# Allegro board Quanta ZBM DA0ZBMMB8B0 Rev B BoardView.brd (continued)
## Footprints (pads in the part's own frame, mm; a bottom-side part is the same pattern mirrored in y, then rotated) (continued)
BGA153-HYNIX-H26M62002JPR-0_5S
  round 0.254 smd: A1(-3.25,-3.25) A2(-3.25,-2.75) A3(-3.25,-2.25) A4(-3.25,-1.75) A5(-3.25,-1.25) A6(-3.25,-0.75) A7(-3.25,-0.25) A8(-3.25,0.25) A9(-3.25,0.75) A10(-3.25,1.25) A11(-3.25,1.75) A12(-3.25,2.25) A13(-3.25,2.75) A14(-3.25,3.25) B1(-2.75,-3.25) B2(-2.75,-2.75) B3(-2.75,-2.25) B4(-2.75,-1.75) B5(-2.75,-1.25) B6(-2.75,-0.75) B7(-2.75,-0.25) B8(-2.75,0.25) B9(-2.75,0.75) B10(-2.75,1.25) B11(-2.75,1.75) B12(-2.75,2.25) B13(-2.75,2.75) B14(-2.75,3.25) C1(-2.25,-3.25) C2(-2.25,-2.75) C3(-2.25,-2.25) C4(-2.25,-1.75) C5(-2.25,-1.25) C6(-2.25,-0.75) C7(-2.25,-0.25) C8(-2.25,0.25) C9(-2.25,0.75) C10(-2.25,1.25) C11(-2.25,1.75) C12(-2.25,2.25) C13(-2.25,2.75) C14(-2.25,3.25) D1(-1.75,-3.25) D2(-1.75,-2.75) D3(-1.75,-2.25) D4(-1.75,-1.75) D12(-1.75,2.25) D13(-1.75,2.75) D14(-1.75,3.25) E1(-1.25,-3.25) E2(-1.25,-2.75) E3(-1.25,-2.25) E5(-1.25,-1.25) E6(-1.25,-0.75) E7(-1.25,-0.25) E8(-1.25,0.25) E9(-1.25,0.75) E10(-1.25,1.25) E12(-1.25,2.25) E13(-1.25,2.75) E14(-1.25,3.25) F1(-0.75,-3.25) F2(-0.75,-2.75) F3(-0.75,-2.25) F5(-0.75,-1.25) F10(-0.75,1.25) F12(-0.75,2.25) F13(-0.75,2.75) F14(-0.75,3.25) G1(-0.25,-3.25) G2(-0.25,-2.75) G3(-0.25,-2.25) G5(-0.25,-1.25) G10(-0.25,1.25) G12(-0.25,2.25) G13(-0.25,2.75) G14(-0.25,3.25) H1(0.25,-3.25) H2(0.25,-2.75) H3(0.25,-2.25) H5(0.25,-1.25) H10(0.25,1.25) H12(0.25,2.25) H13(0.25,2.75) H14(0.25,3.25) J1(0.75,-3.25) J2(0.75,-2.75) J3(0.75,-2.25) J5(0.75,-1.25) J10(0.75,1.25) J12(0.75,2.25) J13(0.75,2.75) J14(0.75,3.25) K1(1.25,-3.25) K2(1.25,-2.75) K3(1.25,-2.25) K5(1.25,-1.25) K6(1.25,-0.75) K7(1.25,-0.25) K8(1.25,0.25) K9(1.25,0.75) K10(1.25,1.25) K12(1.25,2.25) K13(1.25,2.75) K14(1.25,3.25) L1(1.75,-3.25) L2(1.75,-2.75) L3(1.75,-2.25) L12(1.75,2.25) L13(1.75,2.75) L14(1.75,3.25) M1(2.25,-3.25) M2(2.25,-2.75) M3(2.25,-2.25) M4(2.25,-1.75) M5(2.25,-1.25) M6(2.25,-0.75) M7(2.25,-0.25) M8(2.25,0.25) M9(2.25,0.75) M10(2.25,1.25) M11(2.25,1.75) M12(2.25,2.25) M13(2.25,2.75) M14(2.25,3.25) N1(2.75,-3.25) N2(2.75,-2.75) N3(2.75,-2.25) N4(2.75,-1.75) N5(2.75,-1.25) N6(2.75,-0.75) N7(2.75,-0.25) N8(2.75,0.25) N9(2.75,0.75) N10(2.75,1.25) N11(2.75,1.75) N12(2.75,2.25) N13(2.75,2.75) N14(2.75,3.25) P1(3.25,-3.25) P2(3.25,-2.75) P3(3.25,-2.25) P4(3.25,-1.75) P5(3.25,-1.25) P6(3.25,-0.75) P7(3.25,-0.25) P8(3.25,0.25) P9(3.25,0.75) P10(3.25,1.25) P11(3.25,1.75) P12(3.25,2.25) P13(3.25,2.75) P14(3.25,3.25)
BGA200-HYNIX-H9HCNNNCPMMLXR-0_5S
  round 0.254 smd: A1(-6.825,-4.4) A2(-6.825,-3.6) A3(-6.825,-2.8) A4(-6.825,-2) A5(-6.825,-1.2) A8(-6.825,1.2) A9(-6.825,2) A10(-6.825,2.8) A11(-6.825,3.6) A12(-6.825,4.4) AA1(6.175,-4.4) AA2(6.175,-3.6) AA3(6.175,-2.8) AA4(6.175,-2) AA5(6.175,-1.2) AA8(6.175,1.2) AA9(6.175,2) AA10(6.175,2.8) AA11(6.175,3.6) AA12(6.175,4.4) AB1(6.825,-4.4) AB2(6.825,-3.6) AB3(6.825,-2.8) AB4(6.825,-2) AB5(6.825,-1.2) AB8(6.825,1.2) AB9(6.825,2) AB10(6.825,2.8) AB11(6.825,3.6) AB12(6.825,4.4) B1(-6.175,-4.4) B2(-6.175,-3.6) B3(-6.175,-2.8) B4(-6.175,-2) B5(-6.175,-1.2) B8(-6.175,1.2) B9(-6.175,2) B10(-6.175,2.8) B11(-6.175,3.6) B12(-6.175,4.4) C1(-5.525,-4.4) C2(-5.525,-3.6) C3(-5.525,-2.8) C4(-5.525,-2) C5(-5.525,-1.2) C8(-5.525,1.2) C9(-5.525,2) C10(-5.525,2.8) C11(-5.525,3.6) C12(-5.525,4.4) D1(-4.875,-4.4) D2(-4.875,-3.6) D3(-4.875,-2.8) D4(-4.875,-2) D5(-4.875,-1.2) D8(-4.875,1.2) D9(-4.875,2) D10(-4.875,2.8) D11(-4.875,3.6) D12(-4.875,4.4) E1(-4.225,-4.4) E2(-4.225,-3.6) E3(-4.225,-2.8) E4(-4.225,-2) E5(-4.225,-1.2) E8(-4.225,1.2) E9(-4.225,2) E10(-4.225,2.8) E11(-4.225,3.6) E12(-4.225,4.4) F1(-3.575,-4.4) F2(-3.575,-3.6) F3(-3.575,-2.8) F4(-3.575,-2) F5(-3.575,-1.2) F8(-3.575,1.2) F9(-3.575,2) F10(-3.575,2.8) F11(-3.575,3.6) F12(-3.575,4.4) G1(-2.925,-4.4) G2(-2.925,-3.6) G3(-2.925,-2.8) G4(-2.925,-2) G5(-2.925,-1.2) G8(-2.925,1.2) G9(-2.925,2) G10(-2.925,2.8) G11(-2.925,3.6) G12(-2.925,4.4) H1(-2.275,-4.4) H2(-2.275,-3.6) H3(-2.275,-2.8) H4(-2.275,-2) H5(-2.275,-1.2) H8(-2.275,1.2) H9(-2.275,2) H10(-2.275,2.8) H11(-2.275,3.6) H12(-2.275,4.4) J1(-1.625,-4.4) J2(-1.625,-3.6) J3(-1.625,-2.8) J4(-1.625,-2) J5(-1.625,-1.2) J8(-1.625,1.2) J9(-1.625,2) J10(-1.625,2.8) J11(-1.625,3.6) J12(-1.625,4.4) K1(-0.975,-4.4) K2(-0.975,-3.6) K3(-0.975,-2.8) K4(-0.975,-2) K5(-0.975,-1.2) K8(-0.975,1.2) K9(-0.975,2) K10(-0.975,2.8) K11(-0.975,3.6) K12(-0.975,4.4) N1(0.975,-4.4) N2(0.975,-3.6) N3(0.975,-2.8) N4(0.975,-2) N5(0.975,-1.2) N8(0.975,1.2) N9(0.975,2) N10(0.975,2.8) N11(0.975,3.6) N12(0.975,4.4) P1(1.625,-4.4) P2(1.625,-3.6) P3(1.625,-2.8) P4(1.625,-2) P5(1.625,-1.2) P8(1.625,1.2) P9(1.625,2) P10(1.625,2.8) P11(1.625,3.6) P12(1.625,4.4) R1(2.275,-4.4) R2(2.275,-3.6) R3(2.275,-2.8) R4(2.275,-2) R5(2.275,-1.2) R8(2.275,1.2) R9(2.275,2) R10(2.275,2.8) R11(2.275,3.6) R12(2.275,4.4) T1(2.925,-4.4) T2(2.925,-3.6) T3(2.925,-2.8) T4(2.925,-2) T5(2.925,-1.2) T8(2.925,1.2) T9(2.925,2) T10(2.925,2.8) T11(2.925,3.6) T12(2.925,4.4) U1(3.575,-4.4) U2(3.575,-3.6) U3(3.575,-2.8) U4(3.575,-2) U5(3.575,-1.2) U8(3.575,1.2) U9(3.575,2) U10(3.575,2.8) U11(3.575,3.6) U12(3.575,4.4) V1(4.225,-4.4) V2(4.225,-3.6) V3(4.225,-2.8) V4(4.225,-2) V5(4.225,-1.2) V8(4.225,1.2) V9(4.225,2) V10(4.225,2.8) V11(4.225,3.6) V12(4.225,4.4) W1(4.875,-4.4) W2(4.875,-3.6) W3(4.875,-2.8) W4(4.875,-2) W5(4.875,-1.2) W8(4.875,1.2) W9(4.875,2) W10(4.875,2.8) W11(4.875,3.6) W12(4.875,4.4) Y1(5.525,-4.4) Y2(5.525,-3.6) Y3(5.525,-2.8) Y4(5.525,-2) Y5(5.525,-1.2) Y8(5.525,1.2) Y9(5.525,2) Y10(5.525,2.8) Y11(5.525,3.6) Y12(5.525,4.4)
BGA1338-INTEL-JSL
  round 0.356 smd: A4(-16.815,-10.196) A49(-16.815,10.306) A51(-16.815,10.953) B3(-16.255,-10.755) B52(-16.344,11.315) C50(-16.186,10.743) CN1(15.696,-11.315) CN52(15.689,11.315) CP3(16.181,-10.681) CR1(16.352,-11.314) CR50(16.27,10.719) CR52(16.337,11.315) CT2(16.815,-10.843) CT4(16.815,-10.195) CT49(16.815,10.306) CT51(16.815,10.953) D1(-15.696,-11.315) D52(-15.696,11.315)
  round 0.33 smd: A5(-16.815,-9.561) A48(-16.815,9.663) AB17(-7.567,-4.436) AB18(-7.567,-3.712) AB20(-7.567,-2.988) AB21(-7.567,-2.264) AB23(-7.567,-1.541) AB25(-7.567,-0.817) AB33(-7.567,2.803) AB34(-7.567,3.527) AB36(-7.567,4.251) AC17(-6.805,-4.436) AC18(-6.805,-3.712) AC20(-6.805,-2.988) AC21(-6.805,-2.264) AC23(-6.805,-1.541) AC25(-6.805,-0.817) AC33(-6.805,2.803) AC34(-6.805,3.527) AC36(-6.805,4.251) AE17(-6.043,-4.436) AE18(-6.043,-3.712) AE33(-6.043,2.803) AE34(-6.043,3.527) AE36(-6.043,4.251) AG17(-5.281,-4.436) AG18(-5.281,-3.712) AG33(-5.281,2.803) AG34(-5.281,3.527) AG36(-5.281,4.251) AH17(-4.519,-4.436) AH18(-4.519,-3.712) AH33(-4.519,2.803) AH34(-4.519,3.527) AH36(-4.519,4.251) AK17(-3.757,-4.436) AK18(-3.757,-3.712) AK33(-3.757,2.803) AK34(-3.757,3.527) AK36(-3.757,4.251) AM17(-2.995,-4.436) AM18(-2.995,-3.712) AM33(-2.995,2.803) AM34(-2.995,3.527) AM36(-2.995,4.251) AP17(-2.233,-4.436) AP18(-2.233,-3.712) AP33(-2.233,2.803) AP34(-2.233,3.527) AP36(-2.233,4.251) AR17(-1.471,-4.436) AR18(-1.471,-3.712) AR33(-1.471,2.803) AR34(-1.471,3.527) AR36(-1.471,4.251) AU17(-0.709,-4.436) AU18(-0.709,-3.712) AU33(-0.709,2.803) AU34(-0.709,3.527) AU36(-0.709,4.251) AW17(0.053,-4.436) AW18(0.053,-3.712) AW33(0.053,2.803) AW34(0.053,3.527) AW36(0.053,4.251) AY17(0.815,-4.436) AY18(0.815,-3.712) AY20(0.815,-2.988) AY21(0.815,-2.264) AY23(0.815,-1.541) AY33(0.815,2.803) AY34(0.815,3.527) AY36(0.815,4.251) B4(-16.222,-10.162) B5(-16.221,-9.567) BB17(1.577,-4.436) BB18(1.577,-3.712) BB20(1.577,-2.988) BB21(1.577,-2.264) BB23(1.577,-1.541) BB33(1.577,2.803) BB34(1.577,3.527) BB36(1.577,4.251) BD17(2.339,-4.436) BD18(2.339,-3.712) BD20(2.339,-2.988) BD21(2.339,-2.264) BD23(2.339,-1.541) BD33(2.339,2.803) BD34(2.339,3.527) BD36(2.339,4.251) BE17(3.101,-4.436) BE18(3.101,-3.712) BE20(3.101,-2.988) BE21(3.101,-2.264) BE23(3.101,-1.541) BE33(3.101,2.803) BE34(3.101,3.527) BE36(3.101,4.251) BG17(3.863,-4.436) BG18(3.863,-3.712) BG20(3.863,-2.988) BG21(3.863,-2.264) BG23(3.863,-1.541) BG33(3.863,2.803) BG34(3.863,3.527) BG36(3.863,4.251) BJ17(4.625,-4.436) BJ18(4.625,-3.712) BJ20(4.625,-2.988) BJ21(4.625,-2.264) BJ23(4.625,-1.541) BJ33(4.625,2.803) BJ34(4.625,3.527) BJ36(4.625,4.251) BK17(5.387,-4.436) BK18(5.387,-3.712) BK20(5.387,-2.988) BK21(5.387,-2.264) BK23(5.387,-1.541) BK33(5.387,2.803) BK34(5.387,3.527) BK36(5.387,4.251) BM17(6.149,-4.436) BM18(6.149,-3.712) BM20(6.149,-2.988) BM21(6.149,-2.264) BM23(6.149,-1.541) BM33(6.149,2.803) BM34(6.149,3.527) BM36(6.149,4.251) BP17(6.911,-4.436) BP18(6.911,-3.712) BP20(6.911,-2.988) BP21(6.911,-2.264) BP23(6.911,-1.541) BP33(6.911,2.803) BP34(6.911,3.527) BP36(6.911,4.251) BT17(7.673,-4.436) BT18(7.673,-3.712) BT20(7.673,-2.988) BT21(7.673,-2.264) BT23(7.673,-1.541) BT25(7.673,-0.817) BT26(7.673,-0.093) BT28(7.673,0.631) BT30(7.673,1.355) BT31(7.673,2.079) BT33(7.673,2.803) BT34(7.673,3.527) BT36(7.673,4.251) BU17(8.435,-4.436) BU18(8.435,-3.712) BU20(8.435,-2.988) BU21(8.435,-2.264) BU23(8.435,-1.541) BU25(8.435,-0.817) BU26(8.435,-0.093) BU28(8.435,0.631) BU30(8.435,1.355) BU31(8.435,2.079) BU33(8.435,2.803) BU34(8.435,3.527) BU36(8.435,4.251) BW17(9.197,-4.436) BW18(9.197,-3.712) BW20(9.197,-2.988) BW21(9.197,-2.264) BW23(9.197,-1.541) BW25(9.197,-0.817) BW26(9.197,-0.093) BW28(9.197,0.631) BW30(9.197,1.355) BW31(9.197,2.079) BW33(9.197,2.803) BW34(9.197,3.527) BW36(9.197,4.251) C48(-16.181,9.552) C49(-16.186,10.146) CA17(9.959,-4.436) CA18(9.959,-3.712) CA20(9.959,-2.988) CA21(9.959,-2.264) CA23(9.959,-1.541) CA25(9.959,-0.817) CA26(9.959,-0.093) CA28(9.959,0.631) CA30(9.959,1.355) CA31(9.959,2.079) CA33(9.959,2.803) CA34(9.959,3.527) CA36(9.959,4.251) CM1(15.048,-11.315) CM3(14.886,-10.681) CM50(14.975,10.719) CM52(15.053,11.315) CN3(15.533,-10.681) CN50(15.622,10.719) CP4(16.181,-10.043) CP6(16.181,-9.406) CP48(16.181,9.516) CR49(16.243,10.122) CT5(16.815,-9.55) CT48(16.815,9.658) D3(-15.66,-10.72) D50(-15.585,10.722) E1(-15.048,-11.315) E3(-15.066,-10.72) E50(-14.975,10.722) E52(-15.048,11.315) U17(-9.853,-4.436) U18(-9.853,-3.712) U20(-9.853,-2.988) U21(-9.853,-2.264) U23(-9.853,-1.541) U25(-9.853,-0.817) U26(-9.853,-0.093) U28(-9.853,0.631) U30(-9.853,1.355) U31(-9.853,2.079) U33(-9.853,2.803) U34(-9.853,3.527) U36(-9.853,4.251) V17(-9.091,-4.436) V18(-9.091,-3.712) V20(-9.091,-2.988) V21(-9.091,-2.264) V23(-9.091,-1.541) V25(-9.091,-0.817) V26(-9.091,-0.093) V28(-9.091,0.631) V30(-9.091,1.355) V31(-9.091,2.079) V33(-9.091,2.803) V34(-9.091,3.527) V36(-9.091,4.251) Y17(-8.329,-4.436) Y18(-8.329,-3.712) Y20(-8.329,-2.988) Y21(-8.329,-2.264) Y23(-8.329,-1.541) Y25(-8.329,-0.817) Y33(-8.329,2.803) Y34(-8.329,3.527) Y36(-8.329,4.251)
  round 0.305 smd: A7(-16.815,-8.951) A47(-16.815,9.015) AB6(-7.552,-9.208) AB8(-7.552,-8.548) AB9(-7.552,-7.888) AB10(-7.552,-7.228) AB12(-7.552,-6.567) AB13(-7.552,-5.907) AB15(-7.552,-5.247) AB38(-7.234,5.016) AB39(-7.234,5.676) AB41(-7.234,6.337) AB42(-7.234,6.997) AB44(-7.234,7.657) AB45(-7.234,8.317) AD6(-6.472,-9.208) AD8(-6.472,-8.548) AD9(-6.472,-7.888) AD10(-6.472,-7.228) AD12(-6.472,-6.567) AD13(-6.472,-5.907) AD15(-6.472,-5.247) AD38(-6.332,5.016) AD39(-6.332,5.676) AD41(-6.332,6.337) AD42(-6.332,6.997) AD44(-6.332,7.657) AD45(-6.332,8.317) AF38(-5.431,5.016) AF39(-5.431,5.676) AF41(-5.431,6.337) AF42(-5.431,6.997) AF44(-5.431,7.657) AF45(-5.431,8.317) AG6(-5.215,-9.208) AG8(-5.215,-8.548) AG9(-5.215,-7.888) AG10(-5.215,-7.228) AG12(-5.215,-6.567) AG13(-5.215,-5.907) AG15(-5.215,-5.247) AH38(-4.529,5.016) AH39(-4.529,5.676) AH41(-4.529,6.337) AH42(-4.529,6.997) AH44(-4.529,7.657) AH45(-4.529,8.317) AJ6(-4.136,-9.208) AJ8(-4.136,-8.548) AJ9(-4.136,-7.888) AJ10(-4.136,-7.228) AJ12(-4.136,-6.567) AJ13(-4.136,-5.907) AJ15(-4.136,-5.247) AK38(-3.627,5.016) AK39(-3.627,5.676) AK41(-3.627,6.337) AK42(-3.627,6.997) AK44(-3.627,7.657) AK45(-3.627,8.317) AM6(-2.879,-9.208) AM8(-2.879,-8.548) AM9(-2.879,-7.888) AM10(-2.879,-7.228) AM12(-2.879,-6.567) AM13(-2.879,-5.907) AM15(-2.879,-5.247) AM38(-2.726,5.016) AM39(-2.726,5.676) AM41(-2.726,6.337) AM42(-2.726,6.997) AM44(-2.726,7.657) AM45(-2.726,8.317) AP38(-1.824,5.016) AP39(-1.824,5.676) AP41(-1.824,6.337) AP42(-1.824,6.997) AP44(-1.824,7.657) AP45(-1.824,8.317) AR6(-1.799,-9.208) AR8(-1.799,-8.548) AR9(-1.799,-7.888) AR10(-1.799,-7.228) AR12(-1.799,-6.567) AR13(-1.799,-5.907) AR15(-1.799,-5.247) AT38(-0.923,5.016) AT39(-0.923,5.676) AT41(-0.923,6.337) AT42(-0.923,6.997) AT44(-0.923,7.657) AT45(-0.923,8.317) AU6(-0.542,-9.208) AU8(-0.542,-8.548) AU9(-0.542,-7.888) AU10(-0.542,-7.228) AU12(-0.542,-6.567) AU13(-0.542,-5.907) AU15(-0.542,-5.247) AV38(-0.021,5.016) AV39(-0.021,5.676) AV41(-0.021,6.337) AV42(-0.021,6.997) AV44(-0.021,7.657) AV45(-0.021,8.317) AW6(0.36,-9.208) AW8(0.36,-8.548) AW9(0.36,-7.888) AW10(0.36,-7.228) AW12(0.36,-6.567) AW13(0.36,-5.907) AW15(0.36,-5.247) AY38(0.881,5.016) AY39(0.881,5.676) AY41(0.881,6.337) AY42(0.881,6.997) AY44(0.881,7.657) AY45(0.881,8.317) B7(-16.221,-8.974) BA6(1.274,-9.208) BA8(1.274,-8.548) BA9(1.274,-7.888) BA10(1.274,-7.228) BA12(1.274,-6.567) BA13(1.274,-5.907) BA15(1.274,-5.247) BB38(1.782,5.016) BB39(1.782,5.676) BB41(1.782,6.337) BB42(1.782,6.997) BB44(1.782,7.657) BB45(1.782,8.317) BC6(2.176,-9.208) BC8(2.176,-8.548) BC9(2.176,-7.888) BC10(2.176,-7.228) BC12(2.176,-6.567) BC13(2.176,-5.907) BC15(2.176,-5.247) BD38(2.684,5.016) BD39(2.684,5.676) BD41(2.684,6.337) BD42(2.684,6.997) BD44(2.684,7.657) BD45(2.684,8.317) BF6(3.433,-9.208) BF8(3.433,-8.548) BF9(3.433,-7.888) BF10(3.433,-7.228) BF12(3.433,-6.567) BF13(3.433,-5.907) BF15(3.433,-5.247) BF38(3.585,5.016) BF39(3.585,5.676) BF41(3.585,6.337) BF42(3.585,6.997) BF44(3.585,7.657) BF45(3.585,8.317) BH38(4.487,5.016) BH39(4.487,5.676) BH41(4.487,6.337) BH42(4.487,6.997) BH44(4.487,7.657) BH45(4.487,8.317) BJ6(4.512,-9.208) BJ8(4.512,-8.548) BJ9(4.512,-7.888) BJ10(4.512,-7.228) BJ12(4.512,-6.567) BJ13(4.512,-5.907) BJ15(4.512,-5.247) BK38(5.389,5.016) BK39(5.389,5.676) BK41(5.389,6.337) BK42(5.389,6.997) BK44(5.389,7.657) BK45(5.389,8.317) BL6(5.769,-9.208) BL8(5.769,-8.548) BL9(5.769,-7.888) BL10(5.769,-7.228) BL12(5.769,-6.567) BL13(5.769,-5.907) BL15(5.769,-5.247) BM38(6.29,5.016) BM39(6.29,5.676) BM41(6.29,6.337) BM42(6.29,6.997) BM44(6.29,7.657) BM45(6.29,8.317) BP6(6.849,-9.208) BP8(6.849,-8.548) BP9(6.849,-7.888) BP10(6.849,-7.228) BP12(6.849,-6.567) BP13(6.849,-5.907) BP15(6.849,-5.247) BP38(7.192,5.016) BP39(7.192,5.676) BP41(7.192,6.337) BP42(7.192,6.997) BP44(7.192,7.657) BP45(7.192,8.317) BT38(8.093,5.016) BT39(8.093,5.676) BT41(8.093,6.337) BT42(8.093,6.997) BT44(8.093,7.657) BT45(8.093,8.317) BU6(8.106,-9.208) BU8(8.106,-8.548) BU9(8.106,-7.888) BU10(8.106,-7.228) BU12(8.106,-6.567) BU13(8.106,-5.907) BU15(8.106,-5.247) BV38(8.995,5.016) BV39(8.995,5.676) BV41(8.995,6.337) BV42(8.995,6.997) BV44(8.995,7.657) BV45(8.995,8.317) BW6(9.008,-9.208) BW8(9.008,-8.548) BW9(9.008,-7.888) BW10(9.008,-7.228) BW12(9.008,-6.567) BW13(9.008,-5.907) BW15(9.008,-5.247) BY38(9.897,5.016) BY39(9.897,5.676) BY41(9.897,6.337) BY42(9.897,6.997) BY44(9.897,7.657) BY45(9.897,8.317) C46(-16.181,8.913) CA6(9.909,-9.208) CA8(9.909,-8.548) CA9(9.909,-7.888) CA10(9.909,-7.228) CA12(9.909,-6.567) CA13(9.909,-5.907) CA15(9.909,-5.247) CB17(10.553,-4.437) CB19(10.553,-3.536) CB21(10.553,-2.634) CB23(10.553,-1.733) CB24(10.553,-1.022) CB26(10.553,-0.12) CB28(10.553,0.782) CB30(10.553,1.683) CB32(10.553,2.585) CB34(10.553,3.486) CB36(10.553,4.388) CC6(10.811,-9.258) CC7(10.811,-8.598) CC9(10.811,-7.938) CC11(11.122,-7.142) CC13(11.122,-6.241) CC15(11.122,-5.339) CC17(11.213,-4.437) CC19(11.213,-3.536) CC21(11.213,-2.634) CC23(11.213,-1.733) CC24(11.213,-1.022) CC26(11.213,-0.12) CC28(11.213,0.782) CC30(11.213,1.683) CC32(11.213,2.585) CC34(11.213,3.486) CC36(11.213,4.388) CC38(10.798,5.016) CC39(10.798,5.676) CC41(10.798,6.337) CC42(10.798,6.997) CC44(10.798,7.657) CC45(10.798,8.317) CD6(11.653,-9.262) CD7(11.673,-8.66) CD38(11.292,5.346) CD41(11.39,6.401) CD42(11.393,6.996) CE9(11.782,-8.044) CE11(11.782,-7.142) CE13(11.782,-6.241) CE15(11.782,-5.339) CE17(11.873,-4.437) CE19(11.873,-3.536) CE21(11.873,-2.634) CE23(11.873,-1.733) CE24(11.873,-1.022) CE26(11.873,-0.12) CE28(11.873,0.782) CE30(11.873,1.683) CE32(11.873,2.585) CE34(11.873,3.486) CE36(11.873,4.388) CE38(11.883,5.29) CE40(11.762,5.937) CE44(11.784,7.875) CE45(11.784,8.469) CE47(11.784,9.063) CF5(12.215,-9.454) CF7(12.44,-8.905) CF9(12.442,-8.044) CF11(12.442,-7.142) CF13(12.442,-6.241) CF15(12.442,-5.339) CF17(12.533,-4.437) CF19(12.533,-3.536) CF21(12.533,-2.634) CF23(12.533,-1.733) CF24(12.533,-1.022) CF26(12.533,-0.12) CF28(12.533,0.782) CF30(12.533,1.683) CF32(12.533,2.585) CF34(12.533,3.486) CF36(12.533,4.388) CF38(12.533,5.29) CF40(12.282,6.228) CF42(12.455,7.163) CG44(12.736,8.035) CG46(12.76,8.629) CH7(13.053,-8.946) CH9(13.103,-8.044) CH11(13.103,-7.142) CH13(13.103,-6.241) CH15(13.103,-5.339) CH17(13.194,-4.437) CH19(13.194,-3.536) CH21(13.194,-2.634) CH23(13.194,-1.733) CH24(13.194,-1.022) CH26(13.194,-0.12) CH28(13.194,0.782) CH30(13.194,1.683) CH32(13.194,2.585) CH34(13.194,3.486) CH36(13.194,4.388) CH38(13.194,5.29) CH40(13.206,6.128) CH42(13.149,7.147) CH43(13.476,7.641) CJ7(13.713,-8.946) CJ9(13.763,-8.044) CJ11(13.763,-7.142) CJ13(13.763,-6.241) CJ15(13.763,-5.339) CJ17(13.854,-4.437) CJ19(13.854,-3.536) CJ21(13.854,-2.634) CJ23(13.854,-1.733) CJ24(13.854,-1.022) CJ26(13.854,-0.12) CJ28(13.854,0.782) CJ30(13.854,1.683) CJ32(13.854,2.585) CJ34(13.854,3.486) CJ36(13.854,4.388) CJ38(13.854,5.29) CJ40(13.864,6.191) CJ41(13.601,6.725) CJ45(13.761,8.17) CJ46(13.761,8.765) CK3(14.291,-10.732) CK5(14.169,-9.637) CK43(14.134,7.428) CK48(14.047,9.673) CK50(14.327,10.719) CL1(14.4,-11.315) CL4(14.618,-10.151) CL6(14.677,-9.127) CL47(14.521,9.105) CL49(14.634,10.161) CL52(14.405,11.315) CM5(15.214,-9.616) CM7(15.222,-8.621) CM48(15.107,9.693) CN4(15.584,-10.089) CN6(15.667,-9.097) CN47(15.548,9.105) CN49(15.649,10.125) CP7(16.181,-8.798) CP46(16.181,8.908) CT7(16.815,-8.931) CT47(16.815,9.01) D4(-15.629,-10.127) D6(-15.657,-9.18) D47(-15.624,9.125) D49(-15.581,10.127) E5(-15.233,-9.681) E48(-15.135,9.666) F3(-14.47,-10.724) F4(-14.653,-10.159) F6(-14.608,-9.202) F49(-14.558,10.1) F52(-14.429,11.315) G1(-14.4,-11.315) G5(-14.138,-9.859) G50(-14.381,10.668) H6(-13.662,-9.275) H8(-13.698,-8.319) H10(-13.748,-7.475) H12(-13.748,-6.573) H14(-13.748,-5.672) H16(-13.748,-4.77) H18(-13.748,-3.868) H20(-13.748,-2.967) H22(-13.748,-1.887) H24(-13.748,-0.986) H26(-13.748,-0.084) H28(-13.748,0.817) H30(-13.748,1.719) H32(-13.748,2.621) H34(-13.748,3.522) H36(-13.748,4.424) H38(-13.545,5.016) H39(-13.545,5.676) H41(-13.545,6.337) H42(-13.545,6.997) H44(-13.545,7.657) H45(-13.545,8.317) J7(-13.118,-8.927) J8(-13.093,-8.332) J10(-13.088,-7.475) J12(-13.088,-6.573) J14(-13.088,-5.672) J16(-13.088,-4.77) J18(-13.088,-3.868) J20(-13.088,-2.967) J22(-13.088,-1.887) J24(-13.088,-0.986) J26(-13.088,-0.084) J28(-13.088,0.817) J30(-13.088,1.719) J32(-13.088,2.621) J34(-13.088,3.522) J36(-13.088,4.424) K38(-12.644,5.016) K39(-12.644,5.676) K41(-12.644,6.337) K42(-12.644,6.997) K44(-12.644,7.657) K45(-12.644,8.317) L6(-12.25,-9.436) L7(-12.25,-8.843) L8(-12.25,-8.25) L10(-12.427,-7.475) L12(-12.427,-6.573) L14(-12.427,-5.672) L16(-12.427,-4.77) L18(-12.427,-3.868) L20(-12.427,-2.967) L22(-12.427,-1.887) L24(-12.427,-0.986) L26(-12.427,-0.084) L28(-12.427,0.817) L30(-12.427,1.719) L32(-12.427,2.621) L34(-12.427,3.522) L36(-12.427,4.424) M12(-11.767,-6.573) M14(-11.767,-5.672) M16(-11.767,-4.77) M18(-11.767,-3.868) M20(-11.767,-2.967) M22(-11.767,-1.887) M24(-11.767,-0.986) M26(-11.767,-0.084) M28(-11.767,0.817) M30(-11.767,1.719) M32(-11.767,2.621) M34(-11.767,3.522) M36(-11.767,4.424) M38(-11.742,5.016) M39(-11.742,5.676) M41(-11.742,6.337) M42(-11.742,6.997) M44(-11.742,7.657) M45(-11.742,8.317) N6(-11.356,-9.008) N8(-11.356,-8.348) N9(-11.356,-7.688) N11(-11.356,-7.027) P14(-11.107,-5.672) P16(-11.107,-4.77) P18(-11.107,-3.868) P20(-11.107,-2.967) P22(-11.107,-1.887) P24(-11.107,-0.986) P26(-11.107,-0.084) P28(-11.107,0.817) P30(-11.107,1.719) P32(-11.107,2.621) P34(-11.107,3.522) P36(-11.107,4.424) P38(-10.84,5.016) P39(-10.84,5.676) P41(-10.84,6.337) P42(-10.84,6.997) P44(-10.84,7.657) P45(-10.84,8.317) R6(-10.435,-9.208) R8(-10.435,-8.548) R9(-10.435,-7.888) R10(-10.435,-7.228) R12(-10.435,-6.567) R13(-10.435,-5.907) R16(-10.447,-4.77) R18(-10.447,-3.868) R20(-10.447,-2.967) R22(-10.447,-1.887) R24(-10.447,-0.986) R26(-10.447,-0.084) R28(-10.447,0.817) R30(-10.447,1.719) R32(-10.447,2.621) R34(-10.447,3.522) R36(-10.447,4.424) T38(-9.939,5.016) T39(-9.939,5.676) T41(-9.939,6.337) T42(-9.939,6.997) T44(-9.939,7.657) T45(-9.939,8.317) U6(-9.533,-9.208) U8(-9.533,-8.548) U9(-9.533,-7.888) U10(-9.533,-7.228) U12(-9.533,-6.567) U13(-9.533,-5.907) U15(-9.533,-5.247) V38(-9.037,5.016) V39(-9.037,5.676) V41(-9.037,6.337) V42(-9.037,6.997) V44(-9.037,7.657) V45(-9.037,8.317) W6(-8.631,-9.208) W8(-8.631,-8.548) W9(-8.631,-7.888) W10(-8.631,-7.228) W12(-8.631,-6.567) W13(-8.631,-5.907) W15(-8.631,-5.247) Y38(-8.136,5.016) Y39(-8.136,5.676) Y41(-8.136,6.337) Y42(-8.136,6.997) Y44(-8.136,7.657) Y45(-8.136,8.317)
  round 0.279 smd: A8(-16.815,-8.358) A10(-16.815,-7.253) A43(-16.82,7.313) A45(-16.82,8.419) AA2(-7.827,-10.9) AA4(-7.827,-10.071) AA47(-8.099,9.253) AA50(-8.099,10.414) AB3(-7.402,-10.486) AB47(-7.52,9.125) AB48(-7.624,9.709) AB49(-7.328,10.222) AB51(-7.457,10.801) AC2(-6.976,-10.9) AC4(-6.976,-10.071) AC47(-6.95,9.292) AC48(-6.847,9.876) AC50(-6.787,10.466) AD3(-6.551,-10.486) AD47(-6.387,9.105) AE2(-6.125,-10.9) AE4(-6.125,-10.071) AE48(-6.132,9.641) AE49(-6.246,10.223) AE51(-6.148,10.858) AF3(-5.7,-10.486) AF47(-5.684,9.253) AF50(-5.684,10.414) AG2(-5.275,-10.9) AG4(-5.275,-10.071) AG47(-5.105,9.125) AG48(-5.21,9.709) AG51(-5.042,10.801) AH3(-4.849,-10.486) AH47(-4.535,9.292) AH49(-4.913,10.222) AJ2(-4.424,-10.9) AJ4(-4.424,-10.071) AJ48(-4.432,9.876) AJ50(-4.372,10.466) AK3(-3.998,-10.486) AK47(-3.973,9.105) AK48(-3.718,9.641) AK49(-3.831,10.223) AK51(-3.733,10.858) AL2(-3.573,-10.9) AL4(-3.573,-10.071) AL47(-3.269,9.253) AL50(-3.269,10.414) AM2(-2.722,-10.9) AM3(-3.147,-10.486) AM4(-2.722,-10.071) AM48(-2.795,9.709) AN3(-2.296,-10.486) AN47(-2.69,9.125) AN49(-2.498,10.222) AN51(-2.627,10.801) AP2(-1.871,-10.9) AP4(-1.871,-10.071) AP47(-2.121,9.292) AP48(-2.017,9.876) AP50(-1.957,10.466) AR3(-1.446,-10.486) AR47(-1.558,9.105) AR49(-1.416,10.223) AT2(-1.02,-10.9) AT4(-1.02,-10.071) AT48(-1.303,9.641) AT51(-1.318,10.858) AU3(-0.595,-10.486) AU47(-0.854,9.253) AU50(-0.854,10.414) AV2(-0.169,-10.9) AV4(-0.169,-10.071) AV47(-0.275,9.125) AV48(-0.38,9.709) AV49(-0.083,10.222) AV51(-0.213,10.801) AW3(0.256,-10.486) AW47(0.294,9.292) AW48(0.398,9.876) AY2(0.682,-10.9) AY4(0.682,-10.071) AY47(0.857,9.105) AY50(0.458,10.466) B9(-16.313,-7.824) B12(-16.358,-6.648) B14(-16.301,-5.543) B17(-16.358,-4.233) B20(-16.301,-3.128) B22(-16.358,-1.818) B25(-16.301,-0.713) B28(-16.358,0.596) B30(-16.301,1.702) B33(-16.358,3.011) B36(-16.301,4.117) B39(-16.358,5.426) B41(-16.301,6.532) B44(-16.378,8.011) BA3(1.107,-10.486) BA48(1.112,9.641) BA49(0.999,10.223) BA51(1.097,10.858) BB2(1.533,-10.9) BB4(1.533,-10.071) BB47(1.56,9.253) BB50(1.56,10.414) BC3(1.958,-10.486) BC47(2.14,9.125) BC48(2.035,9.709) BC51(2.202,10.801) BD2(2.384,-10.9) BD4(2.384,-10.071) BD49(2.332,10.222) BE3(2.809,-10.486) BE47(2.709,9.292) BE48(2.813,9.876) BE50(2.872,10.466) BF2(3.234,-10.9) BF4(3.234,-10.071) BF47(3.272,9.105) BF48(3.527,9.641) BF49(3.414,10.223) BF51(3.511,10.858) BG3(3.66,-10.486) BG47(3.975,9.253) BG50(3.975,10.414) BH2(4.085,-10.9) BH4(4.085,-10.071) BH48(4.45,9.709) BJ2(4.936,-10.9) BJ3(4.511,-10.486) BJ4(4.936,-10.071) BJ47(4.554,9.125) BJ49(4.746,10.222) BJ51(4.617,10.801) BK3(5.362,-10.486) BK47(5.124,9.292) BK48(5.227,9.876) BK50(5.287,10.466) BL2(5.787,-10.9) BL4(5.787,-10.071) BL47(5.687,9.105) BL49(5.829,10.223) BM3(6.213,-10.486) BM48(5.942,9.641) BM51(5.926,10.858) BN2(6.638,-10.9) BN4(6.638,-10.071) BN47(6.39,9.253) BN50(6.39,10.414) BP3(7.063,-10.486) BP47(6.969,9.125) BP48(6.864,9.709) BP49(7.161,10.222) BP51(7.032,10.801) BR2(7.489,-10.9) BR4(7.489,-10.071) BR47(7.538,9.292) BR48(7.642,9.876) BT3(7.914,-10.486) BT50(7.702,10.466) BU2(8.34,-10.9) BU4(8.34,-10.071) BU47(8.102,9.105) BU48(8.357,9.641) BU49(8.243,10.223) BU51(8.341,10.858) BV3(8.765,-10.486) BV47(8.805,9.253) BV50(8.805,10.414) BW2(9.191,-10.9) BW4(9.191,-10.071) BW47(9.384,9.125) BW48(9.279,9.709) BW51(9.447,10.801) BY3(9.616,-10.486) BY49(9.576,10.222) C8(-16.126,-8.388) C10(-15.965,-7.33) C13(-15.914,-6.184) C16(-15.966,-4.872) C18(-15.914,-3.77) C21(-15.965,-2.457) C23(-15.914,-1.355) C26(-15.965,-0.043) C29(-15.914,1.06) C32(-15.965,2.372) C34(-15.914,3.475) C37(-15.965,4.787) C40(-15.914,5.89) C43(-15.965,7.202) C44(-15.817,7.795) C45(-15.914,8.381) CA2(10.042,-10.9) CA4(10.042,-10.071) CA47(9.953,9.292) CA48(10.057,9.876) CA50(10.117,10.466) CB3(10.467,-10.486) CB47(10.516,9.105) CB48(10.771,9.641) CB49(10.658,10.223) CB51(10.756,10.858) CC2(10.893,-10.9) CC4(10.893,-10.071) CC47(11.22,9.253) CC50(11.22,10.414) CD3(11.318,-10.486) CE2(11.743,-10.9) CE4(11.743,-10.071) CE48(12.059,9.592) CE49(11.701,10.066) CE50(11.894,10.776) CF3(12.169,-10.486) CF49(12.252,10.293) CF52(12.286,11.315) CG1(12.88,-11.315) CG3(12.713,-10.745) CG4(12.632,-10.111) CG47(12.944,9.194) CG48(12.641,9.709) CG49(13.001,10.231) CG51(12.963,10.829) CH2(13.356,-10.929) CH3(13.169,-10.366) CJ1(13.807,-11.315) CJ3(13.751,-10.486) CJ4(13.635,-9.901) CJ47(13.506,9.396) CJ49(13.546,9.995) CJ50(13.733,10.728) CJ52(13.629,11.315) CK45(14.314,8.546) CL8(14.651,-8.465) CL11(14.552,-7.022) CL12(14.492,-6.427) CL14(14.625,-5.57) CL15(14.753,-4.991) CL17(14.605,-4.288) CL18(14.792,-3.725) CL19(14.625,-3.156) CL21(14.753,-2.576) CL22(14.605,-1.873) CL24(14.792,-1.31) CL25(14.625,-0.741) CL26(14.753,-0.162) CL28(14.605,0.542) CL29(14.792,1.105) CL30(14.625,1.674) CL32(14.753,2.253) CL33(14.605,2.957) CL34(14.792,3.519) CL36(14.625,4.089) CL37(14.753,4.668) CL38(14.605,5.371) CL40(14.792,5.934) CL41(14.702,6.521) CL44(14.768,7.79) CM9(15.274,-8.026) CM10(14.908,-7.503) CM11(15.092,-6.772) CM14(15.209,-5.466) CM16(15.141,-4.543) CM20(15.209,-3.051) CM22(15.141,-2.128) CM25(15.209,-0.636) CM27(15.141,0.287) CM30(15.209,1.779) CM33(15.141,2.702) CM36(15.209,4.194) CM38(15.141,5.116) CM41(15.273,6.705) CM43(15.025,7.247) CM45(15.249,8.157) CM46(14.958,8.699) CN11(15.632,-7.029) CN13(15.414,-6.269) CN14(15.722,-5.762) CN17(15.723,-4.43) CN18(15.375,-3.829) CN19(15.722,-3.348) CN22(15.723,-2.015) CN23(15.375,-1.414) CN24(15.722,-0.933) CN27(15.723,0.4) CN29(15.375,1.001) CN30(15.722,1.482) CN33(15.723,2.815) CN34(15.375,3.416) CN35(15.722,3.897) CN38(15.723,5.23) CN39(15.375,5.831) CN41(15.722,6.312) CN43(15.619,7.22) CP8(15.858,-8.17) CP10(15.863,-7.576) CP12(16.065,-6.354) CP15(15.914,-4.991) CP18(15.965,-3.888) CP21(15.914,-2.576) CP23(15.965,-1.474) CP26(15.914,-0.162) CP29(15.965,0.941) CP32(15.914,2.253) CP34(15.965,3.356) CP37(15.914,4.668) CP39(15.965,5.771) CP44(15.75,7.802) CP45(15.914,8.376) CR9(16.382,-7.886) CR11(16.223,-7.104) CR14(16.301,-5.633) CR16(16.358,-4.527) CR19(16.301,-3.218) CR22(16.358,-2.113) CR25(16.301,-0.803) CR27(16.358,0.302) CR30(16.301,1.611) CR33(16.358,2.717) CR35(16.301,4.026) CR38(16.358,5.132) CR41(16.301,6.441) CR43(16.223,7.239) CR44(16.382,8.002) CT8(16.815,-8.338) CT11(16.815,-7.055) CT42(16.815,7.121) CT45(16.815,8.414) D8(-15.559,-8.214) D10(-15.378,-7.232) D11(-15.728,-6.751) D14(-15.723,-5.413) D16(-15.376,-4.932) D17(-15.723,-4.331) D20(-15.722,-2.998) D21(-15.375,-2.517) D22(-15.723,-1.916) D25(-15.722,-0.583) D26(-15.375,-0.103) D28(-15.723,0.499) D31(-15.722,1.831) D32(-15.375,2.312) D33(-15.723,2.913) D36(-15.722,4.246) D37(-15.375,4.727) D38(-15.723,5.328) D41(-15.722,6.661) D42(-15.375,7.142) D45(-15.355,8.172) E7(-15.268,-8.732) E10(-14.933,-7.629) E12(-15.141,-6.633) E14(-15.209,-5.71) E17(-15.141,-4.218) E19(-15.209,-3.295) E22(-15.141,-1.803) E25(-15.209,-0.88) E28(-15.141,0.612) E30(-15.209,1.534) E33(-15.141,3.027) E35(-15.209,3.949) E39(-15.141,5.441) E41(-15.209,6.364) E43(-15.061,7.649) E46(-14.919,8.737) F9(-14.502,-8.056) F12(-14.542,-6.744) F13(-14.753,-6.184) F14(-14.625,-5.605) F15(-14.792,-5.036) F17(-14.606,-4.473) F18(-14.753,-3.77) F19(-14.625,-3.19) F21(-14.792,-2.621) F22(-14.605,-2.058) F23(-14.753,-1.355) F25(-14.625,-0.775) F26(-14.792,-0.206) F27(-14.605,0.357) F29(-14.753,1.06) F30(-14.625,1.639) F31(-14.792,2.209) F33(-14.605,2.772) F34(-14.753,3.475) F36(-14.625,4.054) F37(-14.792,4.623) F38(-14.605,5.186) F40(-14.753,5.89) F41(-14.625,6.469) F43(-14.435,7.614) F45(-14.411,8.214) F47(-14.486,9.159) G7(-14.06,-8.799) G10(-14.364,-7.46) G42(-14.397,7.018) G48(-14.037,9.815) H1(-13.633,-11.315) H3(-13.876,-10.769) H4(-13.661,-10.213) H46(-13.93,8.798) H50(-13.791,10.751) J2(-13.234,-10.873) J4(-13.073,-10.301) J5(-13.125,-9.531) J47(-13.392,9.083) J48(-13.255,9.697) J49(-13.464,10.257) J52(-13.244,11.315) K1(-12.733,-11.315) K3(-12.654,-10.724) K5(-12.646,-9.886) K47(-12.785,9.077) K49(-12.657,10.223) K50(-13.042,10.678) L4(-12.224,-10.311) L48(-12.544,9.641) L51(-12.46,10.813) M2(-12.082,-10.9) M47(-12.136,9.178) M50(-12.019,10.414) M52(-12.139,11.315) N3(-11.656,-10.486) N47(-11.337,9.105) N48(-11.674,9.597) P2(-11.231,-10.9) P3(-10.805,-10.486) P4(-11.231,-10.071) P48(-11.082,9.641) P49(-11.195,10.223) P51(-11.098,10.858) R2(-10.38,-10.9) R4(-10.38,-10.071) R47(-10.634,9.253) R50(-10.634,10.414) T3(-9.955,-10.486) T47(-9.934,9.125) T48(-10.039,9.709) U2(-9.529,-10.9) U4(-9.529,-10.071) U49(-9.742,10.222) U51(-9.872,10.801) V3(-9.104,-10.486) V47(-9.365,9.292) V48(-9.261,9.876) V50(-9.201,10.466) W2(-8.678,-10.9) W4(-8.678,-10.071) W47(-8.802,9.105) W49(-8.66,10.223) W51(-8.563,10.858) Y3(-8.253,-10.486) Y48(-8.547,9.641)
  oval 0.254x0.203 smd: A13(-16.815,-6.184) A16(-16.815,-4.799) A18(-16.815,-3.77) A21(-16.815,-2.384) A23(-16.815,-1.355) A27(-16.815,0.031) A29(-16.815,1.06) A32(-16.815,2.446) A34(-16.815,3.475) A37(-16.815,4.86) A40(-16.815,5.89) CT15(16.815,-4.991) CT18(16.815,-3.962) CT21(16.815,-2.576) CT23(16.815,-1.547) CT26(16.815,-0.162) CT28(16.815,0.868) CT32(16.815,2.253) CT34(16.815,3.283) CT37(16.815,4.668) CT39(16.815,5.697)
  oval 0.203x0.254 smd: AA52(-8.099,11.315) AB1(-7.402,-11.315) AD1(-6.551,-11.315) AD52(-6.713,11.315) AF1(-5.7,-11.315) AF52(-5.684,11.315) AH1(-4.849,-11.315) AJ52(-4.299,11.315) AK1(-3.998,-11.315) AL52(-3.269,11.315) AM1(-3.147,-11.315) AN1(-2.296,-11.315) AP52(-1.884,11.315) AR1(-1.446,-11.315) AU1(-0.595,-11.315) AU52(-0.854,11.315) AW1(0.256,-11.315) AY52(0.531,11.315) BA1(1.107,-11.315) BB52(1.56,11.315) BC1(1.958,-11.315) BE1(2.809,-11.315) BE52(2.946,11.315) BG1(3.66,-11.315) BG52(3.975,11.315) BJ1(4.511,-11.315) BK1(5.362,-11.315) BK52(5.361,11.315) BM1(6.213,-11.315) BN52(6.39,11.315) BP1(7.063,-11.315) BT1(7.914,-11.315) BT52(7.775,11.315) BV1(8.765,-11.315) BV52(8.805,11.315) BY1(9.616,-11.315) CA52(10.19,11.315) CB1(10.467,-11.315) CC52(11.22,11.315) CD1(11.318,-11.315) CF1(12.169,-11.315) N1(-11.656,-11.315) P1(-10.805,-11.315) R52(-10.634,11.315) T1(-9.955,-11.315) V1(-9.104,-11.315) V52(-9.128,11.315) Y1(-8.253,-11.315)
BTB-QSH-030-01-L-D-A-K-TR-60P-RUV
  round 1.016 hole 1.016 unplated: (-10.065,-2.67) (10.065,-2.67)
  rect 0.279x2.261 smd: 1(7.25,2.865) 2(7.25,-2.865) 3(6.75,2.865) 4(6.75,-2.865) 5(6.25,2.865) 6(6.25,-2.865) 7(5.75,2.865) 8(5.75,-2.865) 9(5.25,2.865) 10(5.25,-2.865) 11(4.75,2.865) 12(4.75,-2.865) 13(4.25,2.865) 14(4.25,-2.865) 15(3.75,2.865) 16(3.75,-2.865) 17(3.25,2.865) 18(3.25,-2.865) 19(2.75,2.865) 20(2.75,-2.865) 21(2.25,2.865) 22(2.25,-2.865) 23(1.75,2.865) 24(1.75,-2.865) 25(1.25,2.865) 26(1.25,-2.865) 27(0.75,2.865) 28(0.75,-2.865) 29(0.25,2.865) 30(0.25,-2.865) 31(-0.25,2.865) 32(-0.25,-2.865) 33(-0.75,2.865) 34(-0.75,-2.865) 35(-1.25,2.865) 36(-1.25,-2.865) 37(-1.75,2.865) 38(-1.75,-2.865) 39(-2.25,2.865) 40(-2.25,-2.865) 41(-2.75,2.865) 42(-2.75,-2.865) 43(-3.25,2.865) 44(-3.25,-2.865) 45(-3.75,2.865) 46(-3.75,-2.865) 47(-4.25,2.865) 48(-4.25,-2.865) 49(-4.75,2.865) 50(-4.75,-2.865) 51(-5.25,2.865) 52(-5.25,-2.865) 53(-5.75,2.865) 54(-5.75,-2.865) 55(-6.25,2.865) 56(-6.25,-2.865) 57(-6.75,2.865) 58(-6.75,-2.865) 59(-7.25,2.865) 60(-7.25,-2.865)
  rect 2.54x0.432 smd: 61(8.065,0) 64(-8.065,0)
  rect 4.699x0.432 smd: 62(3.175,0) 63(-3.175,0)
C0201-SMT-TEST
  rect 0.203x0.381 smd: 1(-0.225,0) 2(0.225,0)
C0402
  custom 0.12x0.12 smd: 1(0.39,0) 2(-0.39,0)
C0402_2
  custom 0.12x0.12 smd: 1(0.39,0) 2(-0.39,0)
C0603
  rect 0.686x0.813 smd: 1(0.6,0) 2(-0.6,0)
C0805
  rect 0.864x1.372 smd: 1(0.88,0) 2(-0.88,0)
C3528
  rect 1.6x2.591 smd: 1(1.5,0) 2(-1.5,0)
CHOKE-PHI014B-1R0MS
  rect 0.991x3.81 smd: 1(-1.4,0) 2(1.4,0)
D3-1X0_6-3P
  rect 0.508x0.178 smd: 1(0.401,0.187) 2(0.401,-0.187)
  rect 0.254x0.508 smd: 3(-0.325,0)
D-0_6X0_3-0_32H-SMT
  custom 0.051x0.051 smd: 1(-0.242,0) 2(0.242,0)
D-1_2X0_8-0_7H
  rect 0.61x0.787 smd: 1(-0.85,0) 2(0.85,0)
D-1_2X0_8-0_65H
  rect 0.533x0.508 smd: 1(-0.735,0) 2(0.735,0)
D-1X0_6-0_53H
  rect 0.406x0.711 smd: 1(-0.35,0) 2(0.35,0)
D-1X0_6-2P-PJE24VM5FN2
  rect 0.432x0.61 smd: 1(-0.34,0) 2(0.34,0)
D-SOD123-2_8X1_78
  rect 2.388x1.499 smd: 1(-0.85,0)
  rect 1.041x1.499 smd: 2(1.525,0)
D-SOD323-1_85X1_25-0_95H
  rect 0.559x0.813 smd: 1(-1.15,0) 2(1.15,0)
DFN8-3X2-5-9P-GT24C256B
  rect 0.305x1.194 smd: 1(-0.75,-1.5) 2(-0.25,-1.5) 3(0.25,-1.5) 4(0.75,-1.5) 5(0.75,1.5) 6(0.25,1.5) 7(-0.25,1.5) 8(-0.75,1.5)
  rect 1.397x1.295 smd: 9(0,0)
DFN10-3X3-5-11P-RT9296
  rect 0.305x0.991 smd: 1(-1,-1.6) 2(-0.5,-1.6) 3(0,-1.6) 4(0.5,-1.6) 5(1,-1.6) 6(1,1.6) 7(0.5,1.6) 8(0,1.6) 9(-0.5,1.6) 10(-1,1.6)
  rect 2.464x1.626 smd: 11(0,0)
DFN14-3X2-4-15P-0_8H
  rect 0.203x0.94 smd: 1(-1.2,-1.125) 2(-0.8,-1.125) 3(-0.4,-1.125) 4(0,-1.125) 5(0.4,-1.125) 6(0.8,-1.125) 7(1.2,-1.125) 8(1.2,1.125) 9(0.8,1.125) 10(0.4,1.125) 11(0,1.125) 12(-0.4,1.125) 13(-0.8,1.125) 14(-1.2,1.125)
  rect 2.489x0.787 smd: 15(0,0)
DFN2020-6-2X2-65-7P
  rect 0.533x0.356 smd: 1(0.938,-0.65) 2(0.938,0) 3(0.938,0.65) 4(-0.938,0.65) 5(-0.938,0) 6(-0.938,-0.65)
  rect 0.965x1.702 smd: 7(0,0)
DFN-8L-3X3-65-5P-0_9H
  rect 0.508x0.356 smd: 1(1.4,-0.975) 2(1.4,-0.325) 3(1.4,0.325) 4(1.4,0.975)
  custom 0.57x0.57 smd: 5(-0.51,0)
ESD10-2_5X1-5-0_5H
  rect 0.203x0.483 smd: 1(-1,-0.388) 2(-0.5,-0.388) 3(0,-0.388) 4(0.5,-0.388) 5(1,-0.388) 6(1,0.388) 7(0.5,0.388) 8(0,0.388) 9(-0.5,0.388) 10(-1,0.388)
F4_55X3_24-5_23-1_8H
  rect 1.778x3.505 smd: 1(-2.615,0) 2(2.615,0)
FILTER-BLM03HG601SN1D-SMT
  rect 0.203x0.381 smd: 1(-0.225,0) 2(0.225,0)
FILTER-NFP0QHB542HS2D-4P-SMT
  rect 0.305x0.229 smd: 1(-0.278,-0.212) 2(-0.278,0.212) 3(0.278,0.212) 4(0.278,-0.212)
FPC-50506-00601-V01-6P-L
  rect 0.305x0.889 smd: 1(-1.25,3.05) 2(-0.75,3.05) 3(-0.25,3.05) 4(0.25,3.05) 5(0.75,3.05) 6(1.25,3.05)
  rect 0.991x2.007 smd: 7(-3.35,0) 8(3.35,0)
FPC-51643-0300N-V01-30P-L
  rect 0.305x1.295 smd: 1(-11.6,5.65) 2(-10.8,5.65) 3(-10,5.65) 4(-9.2,5.65) 5(-8.4,5.65) 6(-7.6,5.65) 7(-6.8,5.65) 8(-6,5.65) 9(-5.2,5.65) 10(-4.4,5.65) 11(-3.6,5.65) 12(-2.8,5.65) 13(-2,5.65) 14(-1.2,5.65) 15(-0.4,5.65) 16(0.4,5.65) 17(1.2,5.65) 18(2,5.65) 19(2.8,5.65) 20(3.6,5.65) 21(4.4,5.65) 22(5.2,5.65) 23(6,5.65) 24(6.8,5.65) 25(7.6,5.65) 26(8.4,5.65) 27(9.2,5.65) 28(10,5.65) 29(10.8,5.65) 30(11.6,5.65)
  rect 1.803x2.21 smd: 31(-13.95,0) 32(13.95,0)
FPC-51646-0300N-V01-30P-L
  rect 0.406x1.499 smd: 1(-11.6,1.4) 2(-10.8,1.4) 3(-10,1.4) 4(-9.2,1.4) 5(-8.4,1.4) 6(-7.6,1.4) 7(-6.8,1.4) 8(-6,1.4) 9(-5.2,1.4) 10(-4.4,1.4) 11(-3.6,1.4) 12(-2.8,1.4) 13(-2,1.4) 14(-1.2,1.4) 15(-0.4,1.4) 16(0.4,1.4) 17(1.2,1.4) 18(2,1.4) 19(2.8,1.4) 20(3.6,1.4) 21(4.4,1.4) 22(5.2,1.4) 23(6,1.4) 24(6.8,1.4) 25(7.6,1.4) 26(8.4,1.4) 27(9.2,1.4) 28(10,1.4) 29(10.8,1.4) 30(11.6,1.4)
  rect 2.388x2.388 smd: 31(-14.65,0) 32(14.65,0)
FPC-196650-50041-3-50P-L
  rect 0.305x0.787 smd: 1(-12.25,2.6) 2(-11.75,2.6) 3(-11.25,2.6) 4(-10.75,2.6) 5(-10.25,2.6) 6(-9.75,2.6) 7(-9.25,2.6) 8(-8.75,2.6) 9(-8.25,2.6) 10(-7.75,2.6) 11(-7.25,2.6) 12(-6.75,2.6) 13(-6.25,2.6) 14(-5.75,2.6) 15(-5.25,2.6) 16(-4.75,2.6) 17(-4.25,2.6) 18(-3.75,2.6) 19(-3.25,2.6) 20(-2.75,2.6) 21(-2.25,2.6) 22(-1.75,2.6) 23(-1.25,2.6) 24(-0.75,2.6) 25(-0.25,2.6) 26(0.25,2.6) 27(0.75,2.6) 28(1.25,2.6) 29(1.75,2.6) 30(2.25,2.6) 31(2.75,2.6) 32(3.25,2.6) 33(3.75,2.6) 34(4.25,2.6) 35(4.75,2.6) 36(5.25,2.6) 37(5.75,2.6) 38(6.25,2.6) 39(6.75,2.6) 40(7.25,2.6) 41(7.75,2.6) 42(8.25,2.6) 43(8.75,2.6) 44(9.25,2.6) 45(9.75,2.6) 46(10.25,2.6) 47(10.75,2.6) 48(11.25,2.6) 49(11.75,2.6) 50(12.25,2.6)
  rect 0.991x0.991 smd: 51(-13.55,0) 52(13.55,0)
H-C142D118P2
  round 3.607 hole 2.997: 1(0,0)
H-C150D118P2
  round 3.81 hole 2.997: 1(0,0)
H-C157D157N
  round 3.988 hole 3.988 unplated: (0,0)
H-C256D118P2
  round 6.502 hole 2.997: 1(0,0)
H-C276I158D118P2
  round 7.01 hole 2.997: 1(0,0)
H-O154X142D130X118P2
  oval 3.912x3.607 hole 3.302x2.997: 1(0,0)
H-TC315IBC276D118P2
  round 7.01 hole 2.997: 1(0,0)
H-TC315IC118BC276D118P2
  round 7.01 hole 2.997: 1(0,0)
H-TC354IBC276D118P2
  round 7.01 hole 2.997: 1(0,0)
H-TC354IC244BC276D244P2
  round 7.01 hole 6.198: 1(0,0)
L2_5X2-1_2
  rect 0.787x2.007 smd: 1(-1,0) 2(1,0)
L2X1_6-1_6-1H
  rect 0.787x1.803 smd: 1(-0.8,0) 2(0.8,0)
L4X4-1_8
  rect 1.194x3.708 smd: 1(-1.4,0) 2(1.4,0)
L5_1X5_2-1_6H
  rect 1.905x2.489 smd: 1(-2.047,0) 2(2.047,0)
L6_6X6_6-1_8H
  rect 2.362x3.505 smd: 1(-3.025,0) 2(3.025,0)
L6_6X6_6-2_2H
  rect 2.362x3.505 smd: 1(-3.025,0) 2(3.025,0)
L10_3X10-4H-SMT
  rect 2.413x3.2 smd: 1(-4.75,0) 2(4.75,0)
LED19-337C-RSBHGHC-M01-2T-6P
  rect 0.559x0.406 smd: 1(-0.675,-0.725) 2(0.675,-0.725) 5(-0.675,0.725) 6(0.675,0.725)
  rect 0.711x0.508 smd: 3(-0.75,0) 4(0.75,0)
LGA14-3X2_5-5
  rect 0.254x0.686 smd: 1(-0.75,-1.262) 2(-0.25,-1.262) 3(0.25,-1.262) 4(0.75,-1.262) 8(0.75,1.262) 9(0.25,1.262) 10(-0.25,1.262) 11(-0.75,1.262)
  rect 0.686x0.254 smd: 5(1.012,-0.5) 6(1.012,0) 7(1.012,0.5) 12(-1.012,0.5) 13(-1.012,0) 14(-1.012,-0.5)
MODULE-12X16-152P-SMT
  rect 0.305x0.813 smd: 1(-6.75,-5.752) 2(-6.25,-5.752) 3(-5.75,-5.752) 4(-5.25,-5.752) 5(-4.75,-5.752) 6(-4.25,-5.752) 7(-3.75,-5.752) 8(-3.25,-5.752) 9(-2.75,-5.752) 10(-2.25,-5.752) 11(-1.75,-5.752) 12(-1.25,-5.752) 13(-0.75,-5.752) 14(-0.25,-5.752) 15(0.25,-5.752) 16(0.75,-5.752) 17(1.25,-5.752) 18(1.75,-5.752) 19(2.25,-5.752) 20(2.75,-5.752) 21(3.25,-5.752) 22(3.75,-5.752) 23(4.25,-5.752) 24(4.75,-5.752) 25(5.25,-5.752) 26(5.75,-5.752) 27(6.25,-5.752) 28(6.75,-5.752) 49(6.75,5.752) 50(6.25,5.752) 51(5.75,5.752) 52(5.25,5.752) 53(4.75,5.752) 54(4.25,5.752) 55(3.75,5.752) 56(3.25,5.752) 57(2.75,5.752) 58(2.25,5.752) 59(1.75,5.752) 60(1.25,5.752) 61(0.75,5.752) 62(0.25,5.752) 63(-0.25,5.752) 64(-0.75,5.752) 65(-1.25,5.752) 66(-1.75,5.752) 67(-2.25,5.752) 68(-2.75,5.752) 69(-3.25,5.752) 70(-3.75,5.752) 71(-4.25,5.752) 72(-4.75,5.752) 73(-5.25,5.752) 74(-5.75,5.752) 75(-6.25,5.752) 76(-6.75,5.752)
  rect 0.813x0.305 smd: 29(7.752,-4.75) 30(7.752,-4.25) 31(7.752,-3.75) 32(7.752,-3.25) 33(7.752,-2.75) 34(7.752,-2.25) 35(7.752,-1.75) 36(7.752,-1.25) 37(7.752,-0.75) 38(7.752,-0.25) 39(7.752,0.25) 40(7.752,0.75) 41(7.752,1.25) 42(7.752,1.75) 43(7.752,2.25) 44(7.752,2.75) 45(7.752,3.25) 46(7.752,3.75) 47(7.752,4.25) 48(7.752,4.75) 77(-7.752,4.75) 78(-7.752,4.25) 79(-7.752,3.75) 80(-7.752,3.25) 81(-7.752,2.75) 82(-7.752,2.25) 83(-7.752,1.75) 84(-7.752,1.25) 85(-7.752,0.75) 86(-7.752,0.25) 87(-7.752,-0.25) 88(-7.752,-0.75) 89(-7.752,-1.25) 90(-7.752,-1.75) 91(-7.752,-2.25) 92(-7.752,-2.75) 93(-7.752,-3.25) 94(-7.752,-3.75) 95(-7.752,-4.25) 96(-7.752,-4.75)
  rect 0.711x0.711 smd: 97(-7.5,-5.5) 98(7.5,-5.5) 99(7.5,5.5) 100(-7.5,5.5)
  custom 0.75x0.75 smd: 101(-4.95,-1.65)
  rect 2.997x2.997 smd: 102(-1.65,-1.65) 103(1.65,-1.65) 104(4.95,-1.65) 105(4.95,1.65) 106(1.65,1.65) 107(-1.65,1.65) 108(-4.95,1.65)
  rect 0.305x0.61 smd: A7(-2.75,-3.901) A8(-2.25,-3.901) A9(-1.75,-3.901) A10(-1.25,-3.901) A11(-0.75,-3.901) A12(-0.25,-3.901) A13(0.25,-3.901) A14(0.75,-3.901) A15(1.25,-3.901) A16(1.75,-3.901) A17(2.25,-3.901) A18(2.75,-3.901) A19(3.25,-3.901) A20(3.75,-3.901) A21(4.25,-3.901) A22(4.75,-3.901) A23(5.25,-3.901) A24(5.75,-3.901) A25(6.25,-3.901) A26(6.9,-3.651) A27(6.9,-2.749) A28(6.9,-0.451) A29(6.9,0.451) A30(6.9,2.749) A31(6.9,3.651) A32(6.25,3.901) A33(5.75,3.901) A34(5.25,3.901) A35(4.75,3.901) A36(4.25,3.901) A37(3.75,3.901) A38(3.25,3.901) A39(2.75,3.901) A40(2.25,3.901) A41(1.75,3.901) A42(1.25,3.901) A43(0.75,3.901) A44(0.25,3.901) A45(-0.25,3.901) A46(-0.75,3.901) A47(-1.25,3.901) A48(-1.75,3.901) A49(-2.25,3.901) A50(-2.75,3.901)
P-PHM-08127S-G6-8P-LDV
  rect 0.762x2.388 smd: 1(-1.905,-1.95) 2(-1.905,1.95) 3(-0.635,-1.95) 4(-0.635,1.95) 5(0.635,-1.95) 6(0.635,1.95) 7(1.905,-1.95) 8(1.905,1.95)
PHJK-2SJ3080-123111F-6P
  round 1.295 hole 1.295 unplated: (0,4.225) (0,-0.275)
  oval 0.991x1.905 hole 0.61x1.499: 1(-4.85,7.225) 2(4.7,1.725) 3(-4.85,-0.575) 4(4.7,-1.175) 5(4.7,7.225) 6(4.7,4.475) 7(-4.85,3.125)
POWER-5_2X5_55-1_27-7P-1H
  rect 0.508x0.559 smd: 1(-1.905,-2.8) 5(1.905,2.8) 6(0.635,2.8) 7(-0.635,2.8) 8(-1.905,2.8)
  custom 0.463x0.463 smd: 2(0,-2.1)
  rect 4.648x2.54 smd: 9(0,0.55)
POWER-5_89X4_9-1_27-5P
  rect 1.27x0.61 smd: 1(2.67,-1.905) 2(2.67,-0.635) 3(2.67,0.635) 4(2.67,1.905)
  custom 1.105x1.105 smd: 5(0,0)
POWER-5X6-1_27-7P-0_8H
  rect 0.66x0.635 smd: 1(-1.905,-2.84) 5(1.905,2.84) 6(0.635,2.84) 7(-0.635,2.84) 8(-1.905,2.84)
  custom 0.488x0.488 smd: 2(0,-2.18)
  rect 3.988x2.667 smd: 9(0,0.795)
QFN12-2X2-4
  rect 0.203x1.092 smd: 1(-0.2,-1.05) 2(0.2,-1.05) 7(0.2,1.05) 8(-0.2,1.05)
  rect 1.092x0.203 smd: 3(1.05,-0.6) 4(1.05,-0.2) 5(1.05,0.2) 6(1.05,0.6) 9(-1.05,0.6) 10(-1.05,0.2) 11(-1.05,-0.2) 12(-1.05,-0.6)
QFN12-3X3-45-0_6H
  rect 0.229x0.787 smd: 1(-0.619,-1.5) 6(-0.619,1.5)
  rect 0.229x1.346 smd: 2(0.101,-1.225) 3(1.001,-1.225)
  rect 0.229x2.286 smd: 4(0.551,0.76)
  rect 0.229x2.261 smd: 5(-0.169,0.76)
  rect 0.787x0.229 smd: 7(-1.5,1.125) 8(-1.5,0.675) 9(-1.5,0.225) 10(-1.5,-0.225) 11(-1.5,-0.675) 12(-1.5,-1.125)
QFN16-3X3-5-17P-APW8738A
  rect 0.254x0.787 smd: 1(-0.75,-1.6) 2(-0.25,-1.6) 3(0.25,-1.6) 4(0.75,-1.6) 9(0.75,1.6) 10(0.25,1.6) 11(-0.25,1.6) 12(-0.75,1.6)
  rect 0.787x0.254 smd: 5(1.6,-0.75) 6(1.6,-0.25) 7(1.6,0.25) 8(1.6,0.75) 13(-1.6,0.75) 14(-1.6,0.25) 15(-1.6,-0.25) 16(-1.6,-0.75)
  rect 1.905x1.905 smd: 17(0,0)
QFN16-3X3-5-17P-SLGC55544C
  rect 0.305x0.991 smd: 1(-0.75,-1.6) 2(-0.25,-1.6) 3(0.25,-1.6) 4(0.75,-1.6) 9(0.75,1.6) 10(0.25,1.6) 11(-0.25,1.6) 12(-0.75,1.6)
  rect 0.991x0.305 smd: 5(1.6,-0.75) 6(1.6,-0.25) 7(1.6,0.25) 8(1.6,0.75) 13(-1.6,0.75) 14(-1.6,0.25) 15(-1.6,-0.25) 16(-1.6,-0.75)
  rect 1.702x1.702 smd: 17(0,0)
QFN20-3X3-4-21P-RT6543B
  custom 0.05x0.05 smd: 1(-0.8,-1.475) 5(0.8,-1.475) 6(1.475,-0.8) 10(1.475,0.8) 11(0.8,1.475) 15(-0.8,1.475) 16(-1.475,0.8) 20(-1.475,-0.8)
  rect 0.203x0.838 smd: 2(-0.4,-1.475) 3(0,-1.475) 4(0.4,-1.475) 12(0.4,1.475) 13(0,1.475) 14(-0.4,1.475)
  rect 0.838x0.203 smd: 7(1.475,-0.4) 8(1.475,0) 9(1.475,0.4) 17(-1.475,0.4) 18(-1.475,0) 19(-1.475,-0.4)
  rect 1.702x1.702 smd: 21(0,0)
QFN20-3X3-4-21P-TPD6S300
  custom 0.05x0.05 smd: 1(-0.8,-1.5) 2(-0.4,-1.5) 3(0,-1.5) 4(0.4,-1.5) 5(0.8,-1.5) 6(1.5,-0.8) 7(1.5,-0.4) 8(1.5,0) 9(1.5,0.4) 10(1.5,0.8) 11(0.8,1.5) 12(0.4,1.5) 13(0,1.5) 14(-0.4,1.5) 15(-0.8,1.5) 16(-1.5,0.8) 17(-1.5,0.4) 18(-1.5,0) 19(-1.5,-0.4) 20(-1.5,-0.8)
  rect 1.803x1.803 smd: 21(0,0)
QFN24-4X4-5-25P-TS3A27518ERTWR
  rect 0.305x0.991 smd: 1(-1.25,-2.1) 2(-0.75,-2.1) 3(-0.25,-2.1) 4(0.25,-2.1) 5(0.75,-2.1) 6(1.25,-2.1) 13(1.25,2.1) 14(0.75,2.1) 15(0.25,2.1) 16(-0.25,2.1) 17(-0.75,2.1) 18(-1.25,2.1)
  rect 0.991x0.305 smd: 7(2.1,-1.25) 8(2.1,-0.75) 9(2.1,-0.25) 10(2.1,0.25) 11(2.1,0.75) 12(2.1,1.25) 19(-2.1,1.25) 20(-2.1,0.75) 21(-2.1,0.25) 22(-2.1,-0.25) 23(-2.1,-0.75) 24(-2.1,-1.25)
  rect 2.438x2.438 smd: 25(0,0)
QFN32-4X4-4-33P-RT8845B
  custom 0.05x0.05 smd: 1(-1.4,-2) 8(1.4,-2) 9(2,-1.4) 16(2,1.4) 17(1.4,2) 24(-1.4,2) 25(-2,1.4) 32(-2,-1.4)
  rect 0.203x0.787 smd: 2(-1,-2) 3(-0.6,-2) 4(-0.2,-2) 5(0.2,-2) 6(0.6,-2) 7(1,-2) 18(1,2) 19(0.6,2) 20(0.2,2) 21(-0.2,2) 22(-0.6,2) 23(-1,2)
  rect 0.787x0.203 smd: 10(2,-1) 11(2,-0.6) 12(2,-0.2) 13(2,0.2) 14(2,0.6) 15(2,1) 26(-2,1) 27(-2,0.6) 28(-2,0.2) 29(-2,-0.2) 30(-2,-0.6) 31(-2,-1)
  rect 2.794x2.794 smd: 33(0,0)
QFN32-5X5-5-33P-ALC1015
  rect 0.305x0.991 smd: 1(-1.75,-2.6) 2(-1.25,-2.6) 3(-0.75,-2.6) 4(-0.25,-2.6) 5(0.25,-2.6) 6(0.75,-2.6) 7(1.25,-2.6) 8(1.75,-2.6) 17(1.75,2.6) 18(1.25,2.6) 19(0.75,2.6) 20(0.25,2.6) 21(-0.25,2.6) 22(-0.75,2.6) 23(-1.25,2.6) 24(-1.75,2.6)
  rect 0.991x0.305 smd: 9(2.6,-1.75) 10(2.6,-1.25) 11(2.6,-0.75) 12(2.6,-0.25) 13(2.6,0.25) 14(2.6,0.75) 15(2.6,1.25) 16(2.6,1.75) 25(-2.6,1.75) 26(-2.6,1.25) 27(-2.6,0.75) 28(-2.6,0.25) 29(-2.6,-0.25) 30(-2.6,-0.75) 31(-2.6,-1.25) 32(-2.6,-1.75)
  rect 3.251x3.251 smd: 33(0,0)
QFN40-5X5-4-41P-1H
  rect 0.203x0.61 smd: 1(-1.8,-2.4) 2(-1.4,-2.4) 3(-1,-2.4) 4(-0.6,-2.4) 5(-0.2,-2.4) 6(0.2,-2.4) 7(0.6,-2.4) 8(1,-2.4) 9(1.4,-2.4) 10(1.8,-2.4) 21(1.8,2.4) 22(1.4,2.4) 23(1,2.4) 24(0.6,2.4) 25(0.2,2.4) 26(-0.2,2.4) 27(-0.6,2.4) 28(-1,2.4) 29(-1.4,2.4) 30(-1.8,2.4)
  rect 0.61x0.203 smd: 11(2.4,-1.8) 12(2.4,-1.4) 13(2.4,-1) 14(2.4,-0.6) 15(2.4,-0.2) 16(2.4,0.2) 17(2.4,0.6) 18(2.4,1) 19(2.4,1.4) 20(2.4,1.8) 31(-2.4,1.8) 32(-2.4,1.4) 33(-2.4,1) 34(-2.4,0.6) 35(-2.4,0.2) 36(-2.4,-0.2) 37(-2.4,-0.6) 38(-2.4,-1) 39(-2.4,-1.4) 40(-2.4,-1.8)
  rect 3.607x3.607 smd: 41(0,0)
QFN40-5X5-4-41P-92HD99
  rect 0.203x0.991 smd: 1(-1.8,-2.6) 2(-1.4,-2.6) 3(-1,-2.6) 4(-0.6,-2.6) 5(-0.2,-2.6) 6(0.2,-2.6) 7(0.6,-2.6) 8(1,-2.6) 9(1.4,-2.6) 10(1.8,-2.6) 21(1.8,2.6) 22(1.4,2.6) 23(1,2.6) 24(0.6,2.6) 25(0.2,2.6) 26(-0.2,2.6) 27(-0.6,2.6) 28(-1,2.6) 29(-1.4,2.6) 30(-1.8,2.6)
  rect 0.991x0.203 smd: 11(2.6,-1.8) 12(2.6,-1.4) 13(2.6,-1) 14(2.6,-0.6) 15(2.6,-0.2) 16(2.6,0.2) 17(2.6,0.6) 18(2.6,1) 19(2.6,1.4) 20(2.6,1.8) 31(-2.6,1.8) 32(-2.6,1.4) 33(-2.6,1) 34(-2.6,0.6) 35(-2.6,0.2) 36(-2.6,-0.2) 37(-2.6,-0.6) 38(-2.6,-1) 39(-2.6,-1.4) 40(-2.6,-1.8)
  rect 3.708x3.708 smd: 41(0,0)
QFN40-6X3-4-41P-0_75H
  custom 0.05x0.05 smd: 1(-2.6,-1.425) 14(2.6,-1.425) 15(2.925,-1) 20(2.925,1) 21(2.6,1.425) 34(-2.6,1.425) 35(-2.925,1) 40(-2.925,-1)
  rect 0.203x0.559 smd: 2(-2.2,-1.425) 3(-1.8,-1.425) 4(-1.4,-1.425) 5(-1,-1.425) 6(-0.6,-1.425) 7(-0.2,-1.425) 8(0.2,-1.425) 9(0.6,-1.425) 10(1,-1.425) 11(1.4,-1.425) 12(1.8,-1.425) 13(2.2,-1.425) 22(2.2,1.425) 23(1.8,1.425) 24(1.4,1.425) 25(1,1.425) 26(0.6,1.425) 27(0.2,1.425) 28(-0.2,1.425) 29(-0.6,1.425) 30(-1,1.425) 31(-1.4,1.425) 32(-1.8,1.425) 33(-2.2,1.425)
  rect 0.559x0.203 smd: 16(2.925,-0.6) 17(2.925,-0.2) 18(2.925,0.2) 19(2.925,0.6) 36(-2.925,0.6) 37(-2.925,0.2) 38(-2.925,-0.2) 39(-2.925,-0.6)
  rect 4.496x1.499 smd: 41(0,0)
R0201-SMT-TEST
  rect 0.203x0.381 smd: 1(-0.225,0) 2(0.225,0)
R0402
  custom 0.12x0.12 smd: 1(0.39,0) 2(-0.39,0)
R0603
  rect 0.686x0.813 smd: 1(0.6,0) 2(-0.6,0)
R0805
  rect 0.864x1.372 smd: 1(0.88,0) 2(-0.88,0)
R1206
  rect 1.219x1.626 smd: 1(1.4,0) 2(-1.4,0)
S0201
  rect 0.343x0.381 smd: 1(-0.225,0) 2(0.225,0)
S0402
  custom 0.125x0.125 smd: 1(0.39,0) 2(-0.39,0)
S0603
  rect 1.041x0.813 smd: 1(0.6,0) 2(-0.6,0)
S0805
  rect 1.346x1.372 smd: 1(0.88,0) 2(-0.88,0)
SDCARD-5-251907001000-6-9P-R
  rect 0.66x0.991 smd: 1(2.6,6.9) 2(1.7,6.9) 3(0.8,6.9) 4(-0.1,6.9) 5(-1,6.9) 6(-1.9,6.9) 7(-2.8,6.9) 8(-3.7,6.9)
  rect 0.889x0.991 smd: 9(-5.3,6.9)
  oval 1.092x1.6 hole 0.508x0.965: 10(6.71,0.1)
  oval 1.092x1.803 hole 0.508x1.194: 11(-6.825,6.25) 12(6.825,6.25) 13(6.825,-2.7) 14(-6.825,-2.7)
SENSOR-1_3X0_9-5-4P
  rect 0.457x0.254 smd: 1(-0.625,0.25) 2(-0.625,-0.25) 3(0.625,-0.25) 4(0.625,0.25)
SON4-0_8X0_8-48-5P-0_4H
  custom 0.055x0.055 smd: 1(0.39,-0.24) 2(0.39,0.24) 3(-0.39,0.24) 4(-0.39,-0.24)
  custom 0.088x0.088 smd: 5(0,0)
SON6-1_45X1-5-6P-0_5H
  rect 0.33x0.279 smd: 1(0.3,-0.5) 2(0.3,0) 3(0.3,0.5) 4(-0.3,0.5) 5(-0.3,0) 6(-0.3,-0.5)
SON14-3X2-4-15P-0_85H
  custom 0.05x0.05 smd: 1(-1.2,-1.025) 2(-0.8,-1.025) 3(-0.4,-1.025) 4(0,-1.025) 5(0.4,-1.025) 6(0.8,-1.025) 7(1.2,-1.025) 8(1.2,1.025) 9(0.8,1.025) 10(0.4,1.025) 11(0,1.025) 12(-0.4,1.025) 13(-0.8,1.025) 14(-1.2,1.025)
  rect 2.489x0.889 smd: 15(0,0)
SOT23-1_38-5-3P
  rect 0.533x0.381 smd: 1(0.69,0.5) 2(0.69,-0.5) 3(-0.69,0)
SOT23-2-95-3P
  rect 0.711x0.559 smd: 1(1,0.95) 2(1,-0.95) 3(-1,0)
SOT23-2_8-95-5P-MAX834EUK-T
  rect 1.346x0.508 smd: 1(1.325,-0.95) 2(1.325,0) 3(1.325,0.95) 4(-1.325,0.95) 5(-1.325,-0.95)
SOT23-2_38-95-3P
  rect 0.787x0.533 smd: 1(1.19,0.95) 2(1.19,-0.95) 3(-1.19,0)
SOT23-5-2_8-95-5P-G708
  rect 1.194x0.533 smd: 1(1.5,-0.95) 2(1.5,0) 3(1.5,0.95) 4(-1.5,0.95) 5(-1.5,-0.95)
SOT353-2_1-65-5P-74LVC1G126
  rect 0.61x0.432 smd: 1(0.95,-0.65) 2(0.95,0) 3(0.95,0.65) 4(-0.95,0.65) 5(-0.95,-0.65)
SPAD-C276NP
  round 7.01 smd: 1(0,0)
SPAD-RE130X299NP
  rect 3.302x7.595 smd: 1(0,0)
SPAD-RE213X866NP
  rect 5.41x21.996 smd: 1(0,0)
SPAD-RE236X197NP
  rect 5.994x5.004 smd: 1(0,0)
SPAD-RE517X99NP
  rect 13.132x2.515 smd: 1(0,0)
SPAD-RE591X110NP
  rect 15.011x2.794 smd: 1(0,0)
SPAD-RE591X130NP
  rect 15.011x3.302 smd: 1(0,0)
SPAD-RE669X157NP
  rect 16.993x3.988 smd: 1(0,0)
SPAD-RE1140X157NP
  rect 28.956x3.988 smd: 1(0,0)
SPAD-ZAC-1NP
  custom 0.75x0.75 smd: 1(0,0)
SPAD-ZAC-2NP
  custom 1.075x1.075 smd: 1(0,0)
SW-A205-U-H2-1CTR-3P
  rect 0.94x1.092 smd: 1(-1.225,1.35) 3(1.225,1.35)
  rect 0.61x1.092 smd: 2(0,1.35)
  round 1.194 hole 0.889: 4(-2.125,0) 5(2.125,0)
  rect 1.346x0.711 hole 0.889x0.406: 6(-1.8,-1.1) 7(1.8,-1.1)
TP2050
  round 0.508 smd: 1(0,0)
TSOT23-5-2_7955-9395-5P
  rect 1.346x0.533 smd: 1(1.32,-0.94) 2(1.32,0) 3(1.32,0.94) 4(-1.32,0.94) 5(-1.32,-0.94)
UB3-30154-00902-V01-9P
  round 1.397 hole 0.813: 1(-3.5,6) 2(-1,6) 3(1,6) 4(3.5,6) 5(4,7.5) 6(2,7.5) 7(0,7.5) 8(-2,7.5) 9(-4,7.5)
  oval 1.295x3.2 hole 0.711x2.591: 10(-7.85,0) 11(7.85,0)
  oval 1.295x2.794 hole 0.711x2.21: 12(6.4,7.1) 13(-6.4,7.1)
UB31-UT11113-1220Q-7H-24P
  round 0.813 hole 0.813 unplated: (-3.6,0)
  oval 0.813x0.762 hole 0.813x0.762 unplated: (3.6,0)
  oval 1.041x0.711 hole 0.762x0.406: 1(-3.845,1.55) 2(3.845,1.55)
  oval 0.787x1.397 hole 0.508x1.092: 3(-4.13,-1.25) 4(4.13,-1.25)
  oval 0.991x2.438 hole 0.508x1.499: 5(-4.5,-3.765) 6(4.5,-3.765)
  rect 0.254x0.889 smd: A1(-2.75,0.56) A2(-2.25,0.56) A3(-1.75,0.56) A4(-1.25,0.56) A5(-0.75,0.56) A6(-0.25,0.56) A7(0.25,0.56) A8(0.75,0.56) A9(1.25,0.56) A10(1.75,0.56) A11(2.25,0.56) A12(2.75,0.56)
  round 0.61 hole 0.457: B1(2.8,-0.65) B2(2.4,-1.35) B3(1.6,-1.35) B4(1.2,-0.65) B5(0.8,-1.35) B6(0.4,-0.65) B7(-0.4,-0.65) B8(-0.8,-1.35) B9(-1.2,-0.65) B10(-1.6,-1.35) B11(-2.4,-1.35) B12(-2.8,-0.65)
